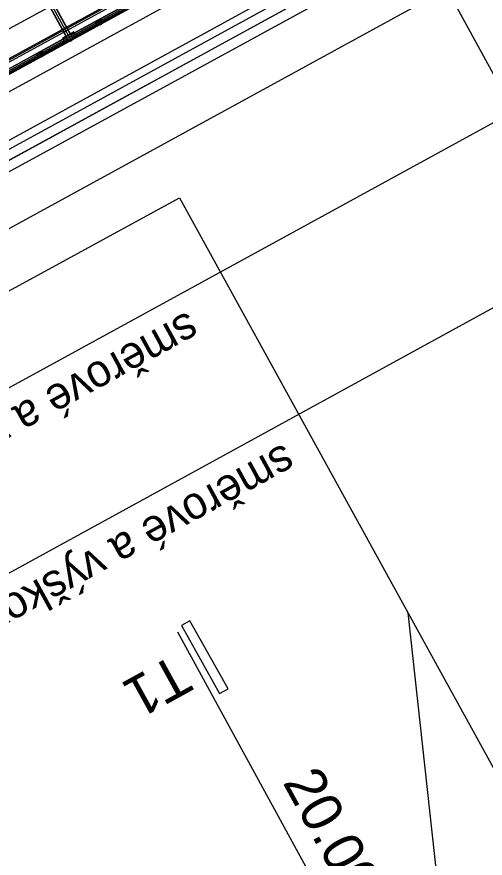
# Model space of a CAD drawing. Extents: x -783978 to -783565, y -1064821 to -1064596.
# Drawn here: x -783764.6 to -783750.16, y -1064707.57 to -1064681.64 of the extents above; entities that cross this region are included whole.
import ezdxf

# ---------------------------------------------------------------- set-up
doc = ezdxf.new("R2010")
doc.units = 0
for name, color, linetype in [('_PS_SO_číslo', 7, 'Continuous'), ('PS 01_02_501', 7, 'Continuous'), ('PS 01_02_502', 7, 'Continuous'), ('SO 01_10_01', 7, 'Continuous'), ('SO 01_20_01', 7, 'Continuous'), ('SO 01_50_01', 7, 'Continuous'), ('SO 01_74_01', 7, 'Continuous'), ('SO 01_77_01', 7, 'Continuous'), ('SO 01_79_02', 7, 'Continuous'), ('SO 01_86_02', 7, 'Continuous'), ('SO 01_86_03', 7, 'Continuous')]:
    doc.layers.add(name, color=color, linetype=linetype)

msp = doc.modelspace()

# ---------------------------------------------------------------- linework, layer by layer
at = {"layer": '_PS_SO_číslo'}
msp.add_line((-783752.544, -1064700.011), (-783748.065, -1064740.955), dxfattribs=at)
at = {"layer": 'PS 01_02_501'}
msp.add_lwpolyline([(-783783.828, -1064700.439), (-783759.588, -1064687.223), (-783745.5, -1064712.799)], dxfattribs=at)
at = {"layer": 'PS 01_02_502'}
msp.add_lwpolyline([(-783783.828, -1064700.439), (-783759.588, -1064687.223), (-783745.5, -1064712.799)], dxfattribs=at)
at = {"layer": 'SO 01_10_01'}
for p, q in [((-783746.877, -1064688.946), (-783768.587, -1064649.261)), ((-783749.277, -1064684.559), (-783793.141, -1064708.557)), ((-783790.742, -1064712.943), (-783746.877, -1064688.946))]:
    msp.add_line(p, q, dxfattribs=at)
at = {"layer": 'SO 01_20_01'}
for p, q in [((-783737.874, -1064667.26), (-783785.335, -1064693.227)), ((-783737.091, -1064667.858), (-783785.781, -1064694.496)), ((-783785.653, -1064694.313), (-783737.23, -1064667.82)), ((-783737.211, -1064667.855), (-783785.634, -1064694.348)), ((-783785.637, -1064694.76), (-783736.947, -1064668.121)), ((-783746.296, -1064673.806), (-783785.835, -1064695.438))]:
    msp.add_line(p, q, dxfattribs=at)
at = {"layer": 'SO 01_50_01'}
msp.add_line((-783759.643, -1064700.6), (-783755.324, -1064708.496), dxfattribs=at)
for points in [[(-783783.629, -1064698.439), (-783735.703, -1064672.219)], [(-783784.775, -1064696.34), (-783745.233, -1064674.706)], [(-783784.655, -1064696.56), (-783745.113, -1064674.926)]]:
    msp.add_lwpolyline(points, dxfattribs=at)
at = {"layer": 'SO 01_74_01'}
for p, q in [((-783785.439, -1064694.663), (-783745.829, -1064672.992)), ((-783745.82, -1064673.01), (-783785.429, -1064694.68)), ((-783763.079, -1064682.247), (-783764.087, -1064680.405)), ((-783763.072, -1064682.243), (-783764.08, -1064680.401)), ((-783763.962, -1064680.337), (-783762.954, -1064682.179)), ((-783763.955, -1064680.333), (-783762.947, -1064682.175)), ((-783760.369, -1064680.793), (-783762.935, -1064682.197)), ((-783760.366, -1064680.799), (-783762.932, -1064682.203)), ((-783762.89, -1064682.279), (-783760.324, -1064680.875)), ((-783762.887, -1064682.285), (-783760.321, -1064680.881)), ((-783762.064, -1064681.863), (-783762.02, -1064681.839)), ((-783762.045, -1064681.898), (-783762.064, -1064681.863)), ((-783762.059, -1064681.872), (-783762.015, -1064681.848)), ((-783762.05, -1064681.889), (-783762.059, -1064681.872)), ((-783762.006, -1064681.865), (-783762.05, -1064681.889)), ((-783762.001, -1064681.874), (-783762.045, -1064681.898)), ((-783762.02, -1064681.839), (-783762.001, -1064681.874)), ((-783762.015, -1064681.848), (-783762.006, -1064681.865)), ((-783762.947, -1064682.175), (-783763.079, -1064682.247)), ((-783762.954, -1064682.179), (-783763.072, -1064682.243)), ((-783762.935, -1064682.197), (-783762.887, -1064682.285)), ((-783762.932, -1064682.203), (-783762.89, -1064682.279)), ((-783763.067, -1064682.269), (-783765.633, -1064683.673)), ((-783763.064, -1064682.275), (-783765.63, -1064683.679)), ((-783765.588, -1064683.755), (-783763.022, -1064682.351)), ((-783765.585, -1064683.761), (-783763.019, -1064682.357)), ((-783763.019, -1064682.357), (-783763.067, -1064682.269)), ((-783763.022, -1064682.351), (-783763.064, -1064682.275)), ((-783762.919, -1064682.331), (-783762.963, -1064682.355)), ((-783762.963, -1064682.355), (-783762.944, -1064682.39)), ((-783762.944, -1064682.39), (-783762.9, -1064682.366)), ((-783762.9, -1064682.366), (-783762.919, -1064682.331)), ((-783763.862, -1064682.847), (-783763.818, -1064682.823)), ((-783763.843, -1064682.882), (-783763.862, -1064682.847)), ((-783763.858, -1064682.856), (-783763.814, -1064682.832)), ((-783763.848, -1064682.873), (-783763.858, -1064682.856)), ((-783763.804, -1064682.849), (-783763.848, -1064682.873)), ((-783763.799, -1064682.858), (-783763.843, -1064682.882)), ((-783763.818, -1064682.823), (-783763.799, -1064682.858)), ((-783763.814, -1064682.832), (-783763.804, -1064682.849))]:
    msp.add_line(p, q, dxfattribs=at)
for points in [[(-783734.088, -1064666.472), (-783786.396, -1064695.09)], [(-783764.093, -1064680.237), (-783762.941, -1064682.343)], [(-783762.107, -1064681.783), (-783762.068, -1064681.855)], [(-783762.076, -1064681.756), (-783762.104, -1064681.771)], [(-783762.102, -1064681.78), (-783762.063, -1064681.851)], [(-783762.073, -1064681.761), (-783762.101, -1064681.776)], [(-783762.09, -1064681.763), (-783762.042, -1064681.851)], [(-783762.044, -1064681.795), (-783762.088, -1064681.819)], [(-783762.03, -1064681.834), (-783762.069, -1064681.762)], [(-783762.025, -1064681.831), (-783762.064, -1064681.759)], [(-783762.059, -1064681.853), (-783762.031, -1064681.838)], [(-783762.056, -1064681.858), (-783762.028, -1064681.843)], [(-783763.068, -1064682.241), (-783762.958, -1064682.181)], [(-783763.065, -1064682.248), (-783762.954, -1064682.188)], [(-783762.911, -1064682.241), (-783763.043, -1064682.313)], [(-783763.013, -1064682.211), (-783762.941, -1064682.343)], [(-783762.949, -1064682.19), (-783762.888, -1064682.3)], [(-783762.942, -1064682.186), (-783762.881, -1064682.296)], [(-783763.013, -1064682.368), (-783763.073, -1064682.258)], [(-783763.006, -1064682.364), (-783763.066, -1064682.254)], [(-783762.89, -1064682.306), (-783763, -1064682.366)], [(-783762.886, -1064682.313), (-783762.996, -1064682.373)], [(-783763.875, -1064682.74), (-783763.902, -1064682.754)], [(-783763.872, -1064682.745), (-783763.899, -1064682.76)], [(-783763.888, -1064682.747), (-783763.84, -1064682.835)], [(-783763.829, -1064682.817), (-783763.867, -1064682.746)], [(-783763.823, -1064682.814), (-783763.862, -1064682.743)], [(-783763.906, -1064682.767), (-783763.867, -1064682.838)], [(-783763.9, -1064682.764), (-783763.861, -1064682.835)], [(-783763.842, -1064682.779), (-783763.886, -1064682.803)], [(-783763.857, -1064682.837), (-783763.83, -1064682.822)], [(-783763.854, -1064682.842), (-783763.827, -1064682.827)]]:
    msp.add_lwpolyline(points, dxfattribs=at)
for points in [[(-783761.954, -1064681.803), (-783762.13, -1064681.899), (-783762.187, -1064681.794), (-783762.012, -1064681.698)], [(-783762.843, -1064682.106), (-783763.193, -1064682.298), (-783763.117, -1064682.439), (-783762.766, -1064682.247)], [(-783763.753, -1064682.787), (-783763.928, -1064682.883), (-783763.986, -1064682.777), (-783763.81, -1064682.681)]]:
    msp.add_lwpolyline(points, close=True, dxfattribs=at)
for centre, radius in [((-783762.147, -1064681.805), 0.006), ((-783762.024, -1064681.738), 0.006), ((-783762.867, -1064682.166), 0.01), ((-783763.13, -1064682.309), 0.01), ((-783763.822, -1064682.722), 0.006), ((-783763.945, -1064682.789), 0.006)]:
    msp.add_circle(centre, radius, dxfattribs=at)
for centre, radius, start, end in [((-783762.099, -1064681.779), 0.00945, 118.6835, 208.6835), ((-783762.099, -1064681.779), 0.00315, 118.6835, 208.6835), ((-783762.072, -1064681.764), 0.00945, 28.6835, 118.6835), ((-783762.072, -1064681.764), 0.00315, 28.6835, 118.6835), ((-783762.06, -1064681.85), 0.00945, 208.6835, 298.6835), ((-783762.06, -1064681.85), 0.00315, 208.6835, 298.6835), ((-783762.033, -1064681.835), 0.00315, 298.6835, 28.6835), ((-783762.033, -1064681.835), 0.00945, 298.6835, 28.6835), ((-783762.952, -1064682.191), 0.012, 28.6835, 118.6835), ((-783762.952, -1064682.191), 0.004, 28.6835, 118.6835), ((-783763.063, -1064682.252), 0.012, 118.6835, 208.6835), ((-783763.063, -1064682.252), 0.004, 118.6835, 208.6835), ((-783763.002, -1064682.362), 0.012, 208.6835, 298.6835), ((-783763.002, -1064682.362), 0.004, 208.6835, 298.6835), ((-783762.892, -1064682.302), 0.004, 298.6835, 28.6835), ((-783762.892, -1064682.302), 0.012, 298.6835, 28.6835), ((-783763.898, -1064682.763), 0.00945, 118.6835, 208.6835), ((-783763.87, -1064682.748), 0.00945, 28.6835, 118.6835), ((-783763.87, -1064682.748), 0.00315, 28.6835, 118.6835), ((-783763.898, -1064682.763), 0.00315, 118.6835, 208.6835), ((-783763.859, -1064682.834), 0.00945, 208.6835, 298.6835), ((-783763.859, -1064682.834), 0.00315, 208.6835, 298.6835), ((-783763.831, -1064682.819), 0.00315, 298.6835, 28.6835), ((-783763.831, -1064682.819), 0.00945, 298.6835, 28.6835)]:
    msp.add_arc(centre, radius, start, end, dxfattribs=at)
at = {"layer": 'SO 01_77_01'}
msp.add_lwpolyline([(-783759.524, -1064700.405), (-783758.348, -1064702.498), (-783758.087, -1064702.351), (-783759.262, -1064700.258), (-783759.524, -1064700.405)], dxfattribs=at)
at = {"layer": 'SO 01_79_02'}
msp.add_lwpolyline([(-783745.082, -1064674.977), (-783746.507, -1064675.757), (-783748.147, -1064676.664), (-783749.691, -1064678.136), (-783784.257, -1064697.013), (-783798.19, -1064704.62), (-783800.06, -1064705.37), (-783802.52, -1064706.72), (-783803.71, -1064707.63), (-783853.11, -1064734.61), (-783855.1, -1064735.3), (-783857.05, -1064736.37), (-783858.65, -1064737.64), (-783871.68, -1064744.75), (-783877.056, -1064744.607), (-783887.429, -1064744.062), (-783898.089, -1064743.49), (-783899.421, -1064743.418)], dxfattribs=at)
at = {"layer": 'SO 01_86_02'}
msp.add_lwpolyline([(-783878.186, -1064744.275), (-783875.129, -1064744.345), (-783874.695, -1064744.328), (-783873.251, -1064744.157), (-783872.314, -1064743.982), (-783871.219, -1064743.702), (-783870.515, -1064743.486), (-783869.798, -1064743.212), (-783869.177, -1064742.975), (-783868.711, -1064742.765), (-783868.395, -1064742.607), (-783868.078, -1064742.449), (-783860.975, -1064738.569), (-783850.672, -1064732.611), (-783846.246, -1064730.189), (-783839.947, -1064727.086), (-783822.426, -1064717.427), (-783813.356, -1064712.518), (-783804.285, -1064707.61), (-783794.474, -1064702.252), (-783784.661, -1064696.896), (-783775.734, -1064692.013), (-783766.806, -1064687.131), (-783750.626, -1064678.282)], dxfattribs=at)
at = {"layer": 'SO 01_86_03'}
msp.add_lwpolyline([(-783747.03, -1064676.621), (-783747.624, -1064677.108), (-783750.73, -1064678.782), (-783751.666, -1064678.852), (-783782.681, -1064695.831), (-783782.888, -1064696.692), (-783783.062, -1064696.82), (-783783.359, -1064696.803), (-783786.817, -1064690.18), (-783787.333, -1064689.237), (-783735.21, -1064660.697), (-783724.821, -1064663.049), (-783722.521, -1064661.793)], dxfattribs=at)

# ---------------------------------------------------------------- texts
at = {"layer": 'SO 01_10_01'}
for p in [(-783759.323, -1064690.703), (-783756.36, -1064694.777)]:
    msp.add_text('směrové a výškové vyrovnání', height=1, rotation=208.7901, dxfattribs=at).set_placement(p)
at = {"layer": 'SO 01_50_01'}
msp.add_text('20.00', height=1.25, rotation=298.6835, dxfattribs=at).set_placement((-783756.417, -1064705.234))
at = {"layer": 'SO 01_77_01'}
msp.add_text('T1', height=1.25, rotation=208.9107, dxfattribs=at).set_placement((-783759.712, -1064701.256))

doc.saveas('drawing.dxf')
